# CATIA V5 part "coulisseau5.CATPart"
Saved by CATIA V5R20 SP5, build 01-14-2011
Part number: coulisseau5
Bounding box of the stored display mesh (mm): x 0 to 10, y -7.5 to 7.5, z -15 to 15
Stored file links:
  E:\IAO_2010\iao\IAO_MMS_Groupe2\IAO_MMS_Groupe2\flafosse\Catia\IAO\coulisseau5.CATPart
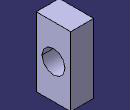
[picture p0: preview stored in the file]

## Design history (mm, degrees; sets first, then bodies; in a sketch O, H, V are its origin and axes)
Body1 (main body)
  Sketch1 on yz-plane, origin (0, 0, 0), H (0, 1, 0), V (0, 0, 1)
    line L1 (7.5, 15) -> (7.5, -15)
    line L2 (7.5, -15) -> (-7.5, -15)
    line L3 (-7.5, -15) -> (-7.5, 15)
    line L4 (-7.5, 15) -> (7.5, 15)
    circle A1 centre (0, 0) radius 5
    length L4 = 15
    radius A1 = 5
    length L1 = 30
    vertical: L1 V, L3 V
    horizontal: L2 H, L4 H
    equidistance: L1 L3 O, L2 L4 O
    perpendicularity: L4 L3
    parallelism: L4 L2
  Pad1: profile Sketch1, direction (1, 0, 0), length 10
  Point1: type Center, Curve edge [end face of Pad1 | face of Pad1 from Sketch1.A1]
